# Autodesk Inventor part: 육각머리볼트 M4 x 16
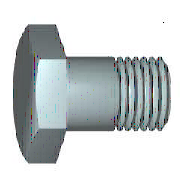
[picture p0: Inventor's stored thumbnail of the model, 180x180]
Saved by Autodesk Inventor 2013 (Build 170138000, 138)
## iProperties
IsCustomPart: 0
Created: 2012-02
Part Number: 육각머리볼트 M4 x 16
Material: 강철, 연강
Description: 6각 머리 볼트 및 6각 머리 나사
Document SubType Name: Modeling
Standard: KS B 1002
Designer: mduedu
Standards Organization: KS
Language: ko-KR
Size Designation: A + B M4 x 16
Categories: <MemberInstance><Categories><Category DisplayName="조임쇠" InternalName="e4da775c-781d-43d5-af7c-5136215cf5a6" Mnemonic="FSTN"><Category DisplayName="볼트" InternalN
Density: 7.86 g/cm^3
Mass: 2.45486 g
Surface Area: 3.4613 cm^2
Volume: 0.312323 cm^3
Author: mduedu
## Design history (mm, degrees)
sketch "스케치1"
  geometry: L1 (0, 2.94)-(0, 2); L2 (2.1, 2)-(16, 2); L3 (16, 2)-(16, 0); L4 (16, 0)-(-0.4, 0); L5 (-3.68, 0)-(19.28, 0) reference; L6 (-0.4, 0)-(-0.4, 2.94); L7 (-0.4, 2.94)-(0, 2.94); L8 (2.1, 2)-(1.67, 2); L9 (1.67, 2)-(0, 2); L10 (0, -0.588)-(0, 3.528) reference
  constraints: 16 end point, 2 collinear, 2 perpendicular, 1 parallel
  dimensions: "d0" = 16 distance between parallel lines of L3 L1 (= NLG); "d1" = 13.9 distance from line of L2.start L3 (= GEL); "d2" = 4 diameter of L2 L4 (= GD); "d9" = 0.4001 distance between parallel lines of L6 L1 (computed from SD); "d10" = 5.88 diameter of L7 L4 (= SD2); "d13" = 0.42952 distance of L2.start L8.end (computed from GAL); "d14" = 4 diameter of L9 L4 (= BDM)
revolve "본체" sketch "스케치1" stored, may be unused: angle "d12" = 90 deg
sketch "스케치2"
  geometry: L1 (0, 4.041)-(3.5, 2.021); L2 (3.5, 2.021)-(3.5, -2.021); L3 (3.5, -2.021)-(0, -4.041); L4 (0, -4.041)-(-3.5, -2.021); L5 (-3.5, -2.021)-(-3.5, 2.021); L6 (-3.5, 2.021)-(0, 4.041); 2 further points
  constraints: 12 end point, 1 coincident, 1 vertical, 11 other
  dimensions: "d11" = 7 distance between parallel lines of L5 L2 (= SW)
extrude "머리" join sketch "스케치2" distance "d3" = 2.4 (= KOH - SD); taper "d4" = 0 deg
sketch "스케치4"
  geometry: L1 (-2.8, 3.5)-(-2.8, 4.041); L2 (-2.8, 4.041)-(-2.487, 4.041); L3 (-2.487, 4.041)-(-2.8, 3.5); L4 (-3.28, 0)-(0.08, 0) reference; L5 (-0.4, 4.041)-(-2.8, 4.041) reference; L6 (-2.8, 2.021)-(-2.8, 4.041) reference
  constraints: 6 end point, 2 collinear, 1 perpendicular, 1 vertical
  dimensions: "d5" = 30 deg angle of L3 L1 (= ANG1); "d19" = 7 diameter of L1.start L4 (= SW0)
revolve "모따기1" sketch "스케치4" stored, may be unused: angle "d21" = 90 deg
workplane "Work Plane1"
body "Solid1"
feature "스레드" dims "d15" = 13.9 (= GEL), "d16" = 0
chamfer "모따기2" distance "d6" = 0.42941 (= -0.5 x SPD + 0.5 x GD); stored, may be unused: second distance "d7" = 0.42952 (computed from GUL), angle "d55" = 45 deg
other parameters: "NLG" = 16 [user parameter; used in 1 equation term], "GD" = 4 (= NND) [user parameter; used in 2 equation terms], "BDM" = 4 (= NND) [user parameter; used in 1 equation term], "KOH" = 2.8 [user parameter; used in 1 equation term], "GEL" = 13.9 [user parameter; used in 2 equation terms], "SW" = 7 [user parameter; used in 3 equation terms], "SW0" = 7 (= SW) [user parameter; used in 1 equation term], "SPD" = 3.14117 (= NND - 1.2269 x PTC) [user parameter; used in 1 equation term], "SD2" = 5.88 (= SDH) [user parameter; used in 1 equation term], "SD" = 0.4 [user parameter; used in 2 equation terms], "ANG1" = 30 deg [user parameter; used in 1 equation term], "GAL" = 0.42941 (= 0.61345 x PTC) [user parameter; used in 1 equation term], "GUL" = 0.42941 (= 0.61345 x PTC) [user parameter; used in 1 equation term], "d8" = 0, "RR" = 0.2 [user parameter], "d57" = 0, "d58" = 0, "TPU" = 14.28571 (computed from PTC) [user parameter], "GD1" = 3.14117 (= THREADDIA - 1.2269 x PTC) [user parameter], "THREADDIA" = 4 [user parameter; used in 1 equation term], "SDH" = 5.88 [user parameter; used in 1 equation term], "SDHG" = 2.1 [user parameter], "TOA" = 30 deg [user parameter], "PTC" = 0.7 [user parameter; used in 5 equation terms], "NND" = 4 [user parameter; used in 3 equation terms], "E0" = 8.085 (= 1.155 x SW) [user parameter]
